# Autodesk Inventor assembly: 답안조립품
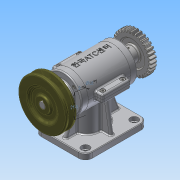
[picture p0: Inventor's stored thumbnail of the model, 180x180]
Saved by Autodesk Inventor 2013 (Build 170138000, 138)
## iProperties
Created: 2015-09
Part Number: 답안조립품
Document SubType Name: Assembly
Designer: Administrator
Author: Administrator
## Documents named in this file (17)
- C:\Users\Administrator\Desktop\350908V1008\답안조립품.iam
- C:\Users\Administrator\Desktop\350908V1008\본체.ipt
- C:\Users\Administrator\Desktop\350908V1008\본체 커버.ipt
- C:\Users\Administrator\Desktop\350908V1008\M4x0.5x14.ipt
- C:\Users\Administrator\Desktop\350908V1008\뒤커버.ipt
- C:\Users\Administrator\Desktop\350908V1008\앞커버.ipt
- C:\Users\Administrator\Desktop\350908V1008\베어링 6201.ipt
- C:\Users\Administrator\Desktop\350908V1008\베어링 6202.ipt
- C:\Users\Administrator\Desktop\350908V1008\오일실.ipt
- C:\Users\Administrator\Desktop\350908V1008\M3x0.5x8.ipt
- C:\Users\Administrator\Desktop\350908V1008\편심축.ipt
- C:\Users\Administrator\Desktop\350908V1008\키4x4.ipt
- C:\Users\Administrator\Desktop\350908V1008\V-벨트풀리.ipt
- C:\Users\Administrator\Desktop\350908V1008\스퍼기어.ipt
- C:\Users\Administrator\Desktop\350908V1008\멈춤나사.ipt
- C:\Users\Administrator\Desktop\350908V1008\슬라이드.ipt
- C:\Users\Administrator\Desktop\350908V1008\가변스프링-1.ipt
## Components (14 placed, 4 different names)
1. M4x0.5x14:1
2. M4x0.5x14:2
3. M4x0.5x14:3
4. M4x0.5x14:4
5. V-벨트풀리:1 — 각도:3, 구동부
6. 가변스프링-1:1
7. M3x0.5x8:1
8. M3x0.5x8:3
9. M3x0.5x8:4
10. M3x0.5x8:5
11. M3x0.5x8:2
12. M3x0.5x8:6
13. M3x0.5x8:7
14. M3x0.5x8:8
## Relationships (2: Angle 2)
- 각도:3 [Angle]: V-벨트풀리:1
- 구동부 [Angle]: V-벨트풀리:1
